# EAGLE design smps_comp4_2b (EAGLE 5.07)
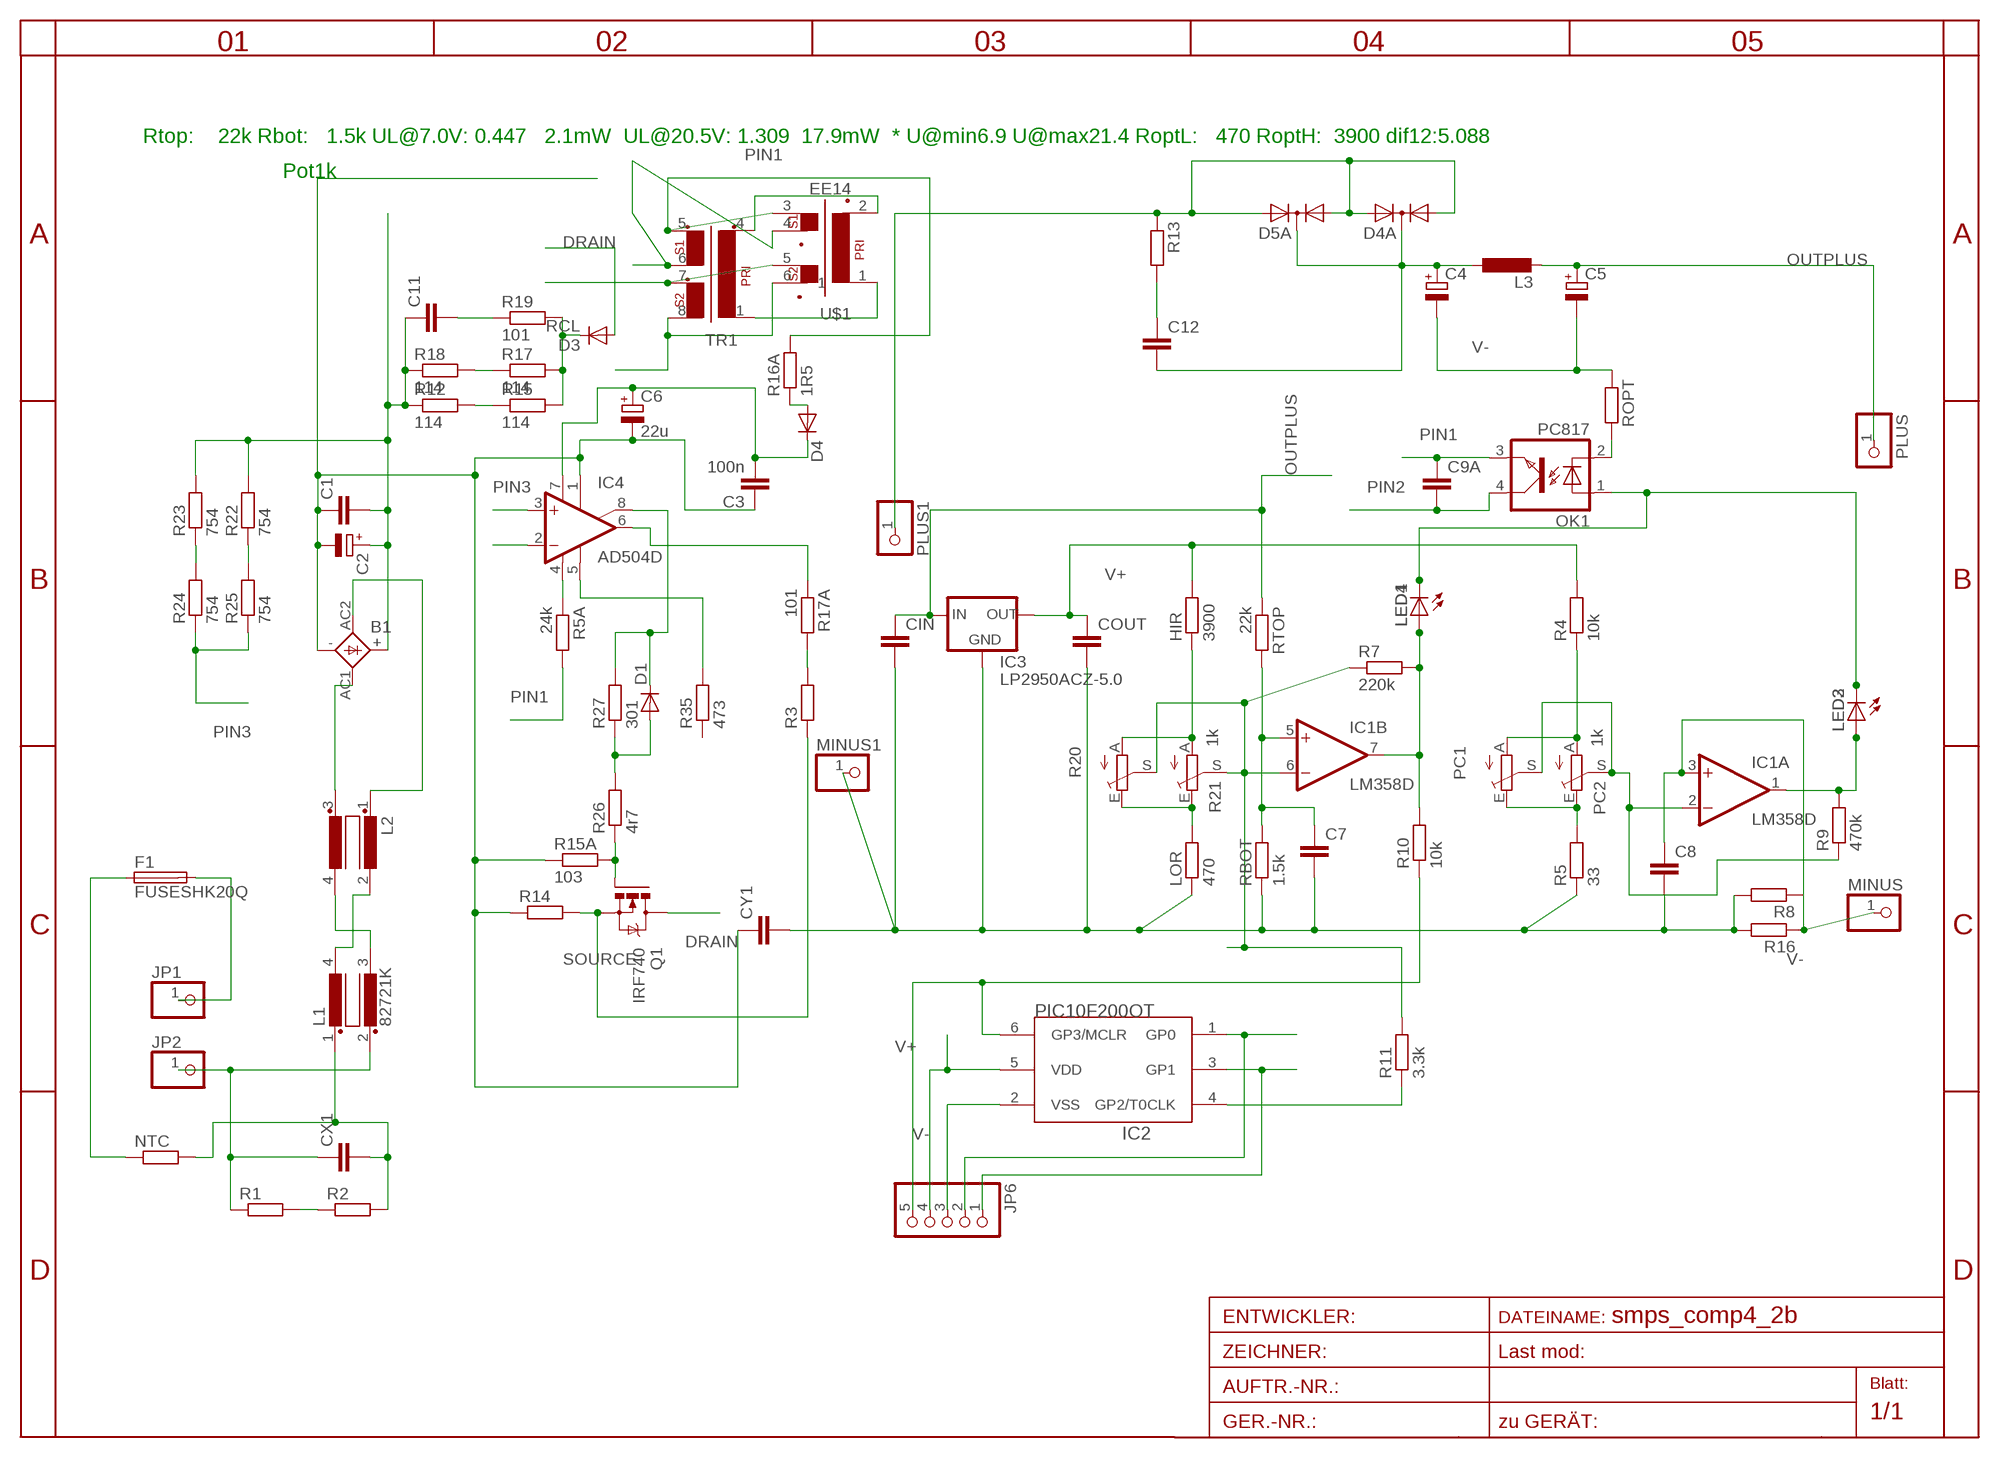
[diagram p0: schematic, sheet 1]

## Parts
B1  KBL  [KBL]
C1  C-EU050-024X044  [C050-024X044]
C2  CPOL-EUE10-25  [EB25D]
C3  100n  C-EUC0805  [C0805]
C4  CPOL-EUE5-8.5  [E5-8,5]
C5  CPOL-EUE5-8.5  [E5-8,5]
C6  22u  CPOL-EUE2.5-6  [E2,5-6]
C7  C-EUC0805  [C0805]
C8  C-EUC0805  [C0805]
C9A  C-EUC0805  [C0805]
C11  C-EUC1206  [C1206]
C12  C-EUC0805  [C0805]
CIN  C-EUC1206  [C1206]
COUT  C-EUC1206  [C1206]
CX1  C-EU150-084X183  [C150-084X183]
CY1  C-EU075-063X106  [C075-063X106]
D1  DIODE-MINIMELF  [MINIMELF]
D3  RCL  1N4004  [DO41-10]
D4  DIODE-MINIMELF  [MINIMELF]
D4A  DIODE-2AC|CAIW220V  [IW220ABS]
D5A  DIODE-2AC|CAIW220V  [IW220ABS]
F1  FUSESHK20Q  [SHK20Q]
HIR  3900  R-EU_R0805  [R0805]
IC1  LM358D  [SO08]
IC2  PIC10F200OT  [SOT23-6]
IC3  LP2950ACZ-5.0  [TO92]
IC4  AD504D  [SO08]
JP1  PINHD-1X12MM2  [1X2MM2]
JP2  PINHD-1X12MM2  [1X2MM2]
JP6  PINHD-1X5/90  [1X05/90]
L1  82721K  [82721K]
L2  R1405VB1/2  [B1/2]
L3  L-EU0207/12  [0207/12]
LED1  LED3MM  [LED3MM]
LED2  LED3MM  [LED3MM]
LED3  LEDCHIPLED_1206  [CHIPLED_1206]
LED4  LEDCHIPLED_1206  [CHIPLED_1206]
LOR  470  R-EU_R0805  [R0805]
MINUS  PINHD-1X12MM2  [1X2MM2]
MINUS1  PINHD-1X11X0.4  [1X01]
NTC  R-EU_0204/7  [0204/7]
OK1  PC817  [DIL04]
PC1  TRIM_EU-S64W  [S64W]
PC2  1k  TRIM_EU-CA6V  [CA6V]
PLUS  PINHD-1X12MM2  [1X2MM2]
PLUS1  PINHD-1X11X0.4  [1X01]
Q1  IRF740  [TO220BV]
R1  R-EU_R1206  [R1206]
R2  R-EU_R1206  [R1206]
R3  R-EU_0207/40  [0207/40]
R4  10k  R-EU_R0805  [R0805]
R5  33  R-EU_R0805  [R0805]
R5A  24k  R-EU_R0805  [R0805]
R7  220k  R-EU_R0805  [R0805]
R8  R-EU_R2010  [R2010]
R9  470k  R-EU_R0805  [R0805]
R10  10k  R-EU_0207/15  [0207/15]
R11  3.3k  R-EU_0207/15  [0207/15]
R12  114  R-EU_R1206  [R1206]
R13  R-EU_R0805  [R0805]
R14  R-EU_0411/3V  [0411V]
R15  114  R-EU_R1206  [R1206]
R15A  103  R-EU_R1206  [R1206]
R16  R-EU_R2010  [R2010]
R16A  1R5  R-EU_R1206  [R1206]
R17  114  R-EU_R1206  [R1206]
R17A  101  R-EU_R0805  [R0805]
R18  114  R-EU_R1206  [R1206]
R19  101  R-EU_R1206  [R1206]
R20  TRIM_EU-S64W  [S64W]
R21  1k  TRIM_EU-CA6V  [CA6V]
R22  754  R-EU_R1206  [R1206]
R23  754  R-EU_R1206  [R1206]
R24  754  R-EU_R1206  [R1206]
R25  754  R-EU_R1206  [R1206]
R26  4r7  R-EU_R1206  [R1206]
R27  301  R-EU_R1206  [R1206]
R35  473  R-EU_R1206  [R1206]
RBOT  1.5k  R-EU_R0805  [R0805]
ROPT  R-EU_R0805  [R0805]
RTOP  22k  R-EU_R0805  [R0805]
TR1  EE20-2  [EE20-2]
U$1  EE14  [EE14]

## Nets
A: PC1.A PC2.A R4.1
A1: HIR.1 R20.A R21.A
CPLUS: C4.+ C12.2 D4A.C D5A.C L3.1
DRAIN: D3.A Q1.D TR1.8 U$1.6
E: PC1.E PC2.E R5.2
E1: LOR.2 R20.E R21.E
N$1: CX1.2 L1.1 NTC.2 R2.2
N$2: CX1.1 JP2.1 L1.2 R1.1
N$3: F1.2A JP1.1
N$5: L1.4 L2.2
N$6: R1.2 R2.1
N$7: B1.AC1(AC2) L2.3
N$9: F1.1A NTC.1
N$10: IC1.6(B:-IN) R7.1 R11.2 R20.S R21.S
N$11: IC1.1(A:OUT) LED2.A LED3.A R9.2
N$12: OK1.2(C) ROPT.2
N$13: LED1.K(C) LED2.K(C) LED3.C LED4.C OK1.1(A)
N$14: L1.3 L2.4
N$15: IC2.6(GP3/MCLR) JP6.5 R10.1
N$16: C7.1 IC1.5(B:+IN) RBOT.2 RTOP.2
N$17: IC2.1(GP0) JP6.2
N$18: IC2.3(GP1) JP6.1
N$19: IC2.4(GP2/T0CLK) R11.1
N$20: B1.AC2(AC1) L2.1
N$21: Q1.G R15A.2 R26.1
N$22: TR1.4 U$1.2
N$23: C11.2 R19.1
N$24: D3.C R15.2 R17.2 R19.2
N$25: D1.A R26.2 R27.1
N$26: R17.1 R18.2
N$27: C12.1 R13.2
N$28: R12.2 R15.1
N$29: R22.1 R25.2
N$30: IC4.4(V-) R5A.1
N$31: R23.1 R24.2
N$32: IC4.6(OUT) R17A.1
N$33: D1.C IC4.8(ON2) R27.2
N$34: R3.2 R17A.2
N$37: D4.A R16A.1
N$38: TR1.1 U$1.1
OUT: C8.1 IC1.3(A:+IN) MINUS.1 R8.1 R16.1
OUTB: IC1.7(B:OUT) LED1.A LED4.A R7.2 R10.2
OUTPLUS: C5.+ CIN.1 IC3.3(IN) L3.2 PLUS.1 RTOP.1
PIN1: B1.- C1.1 C2.- C3.1 C6.- C9A.1 CY1.1 IC4.1(ON1) OK1.3(EMIT) R5A.2 R14.1 R15A.1 TR1.7 U$1.5
PIN2: C9A.2 IC4.2(-IN) OK1.4(COL)
PIN3: IC4.3(+IN) R24.1 R25.1
PIN5: IC4.5(OPT) R35.2
PIN7: C3.2 C6.+ D4.C IC4.7(V+)
PLUS: B1.+ C1.2 C2.+ C11.1 R12.1 R18.1 R22.2 R23.2 TR1.6 U$1.4
S: IC1.2(A:-IN) PC1.S PC2.S R9.1
SOURCE: Q1.S R3.1 R14.2
TPLUS: D4A.A1 D4A.A2 D5A.A1 D5A.A2 PLUS1.1 R13.1
V+: COUT.1 HIR.2 IC2.5(VDD) IC3.1(OUT) JP6.4 R4.2
V-: C4.- C5.- C7.2 C8.2 CIN.2 COUT.2 CY1.2 IC2.2(VSS) IC3.2(GND) JP6.3 LOR.1 MINUS1.1 R5.1 R8.2 R16.2 RBOT.1 ROPT.1
X: R16A.2 TR1.5 U$1.3
Unconnected: R35.1

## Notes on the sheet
- Rtop:    22k Rbot:   1.5k UL@7.0V: 0.447   2.1mW  UL@20.5V: 1.309  17.9mW  * U@min6.9 U@max21.4 RoptL:   470 RoptH:  3900 dif12:5.088
- Pot1k

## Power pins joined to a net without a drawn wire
V+: IC1.8(P:V+)
V-: IC1.4(P:V-)

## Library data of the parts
B1 = rectifier:KBL: DIOTEC RECTIFIER
C1 C3 C7 C8 C9A C11 C12 CIN COUT CX1 CY1 = rcl:C-EU: CAPACITOR, European symbol
C2 C4-C6 = rcl:CPOL-EU: POLARIZED CAPACITOR, European symbol
D1 D4 = diode:DIODE-: DIODE
D3 = diode:1N4004: DIODE
D4A D5A = diode:DIODE-2AC|CA: Dual DIODE Anode-Cathode|Cathode-Anode
F1 = fuse:FUSE: Fuse
HIR LOR NTC R1 R2 R4 R5 R5A R7-R15 R15A R16 R16A R17 R17A R18 R19 R22-R27 R35 RBOT ROPT RTOP = rcl:R-EU_: RESISTOR, European symbol
IC1 = linear:LM358: OP AMP also LM158; LM258; LM2904 Source: http://cache.national.com/ds/LM/LM158.pdf
IC2 = microchip-5:PIC10F20*: uPC nW 0,25/0,5k Program Flash memory
IC3 = v-reg:LP2950?*: Source: http://cache.national.com/ds/LP/LP2950.pdf
IC4 = linear:AD504: OP AMP
JP1 JP2 MINUS MINUS1 PLUS PLUS1 = pinhead:PINHD-1X1: PIN HEADER
JP6 = pinhead:PINHD-1X5: PIN HEADER
L1 = inductors:82721K: FILTER
L2 = inductor-nkl:R1405V: Übertrager (verlustarm) bis typ. 400kHz Power transformer (low loss) up to typ. 400kHz
L3 = rcl:L-EU: INDUCTOR, European symbol
LED1-LED4 = led:LED: LED
OK1 = optocoupler:PC817: SHARP OPTO COUPLER
PC1 PC2 R20 R21 = pot:TRIM_EU-: POTENTIOMETER
Q1 = transistor-power:IRF740: N-CHANNEL MOS FET
R3 = rcl-2:R-EU_: RESISTOR, European symbol
TR1 = trafo:EE20-2: TRANSFORMER 1 primary winding, 2 secondary windings ERA
U$1 = trafo:EE14

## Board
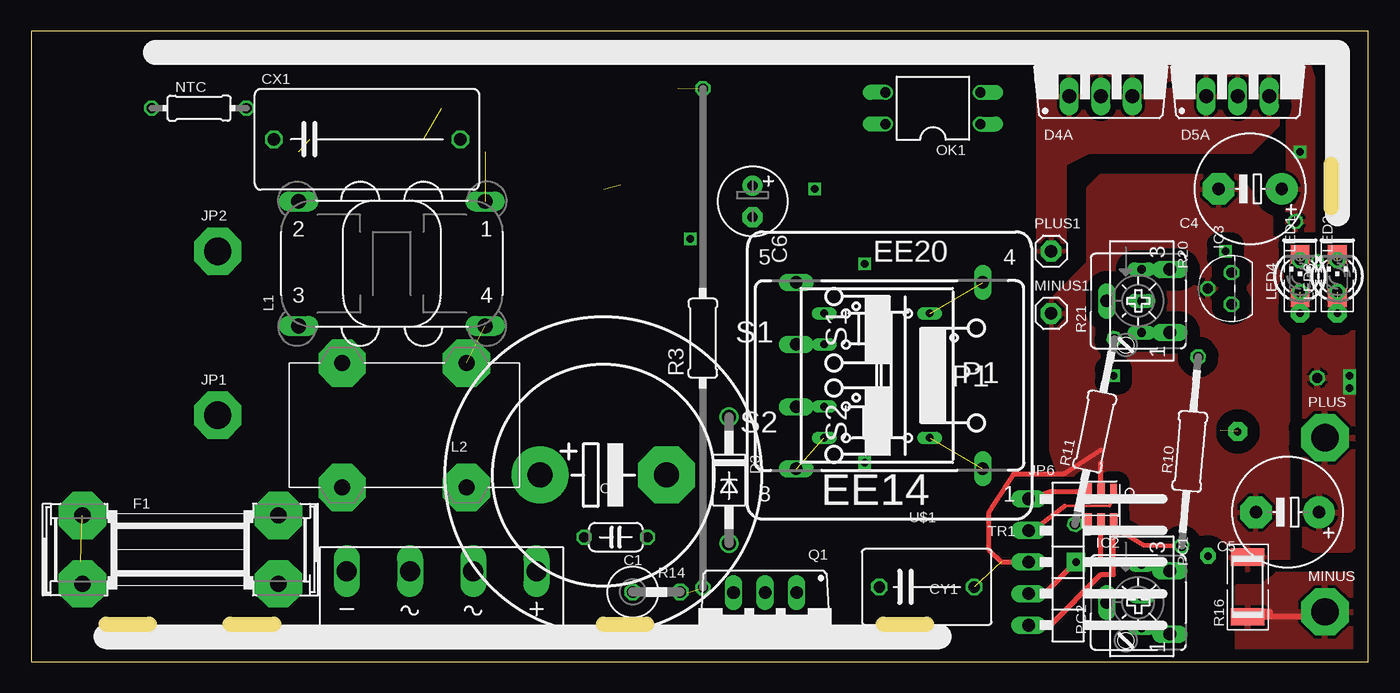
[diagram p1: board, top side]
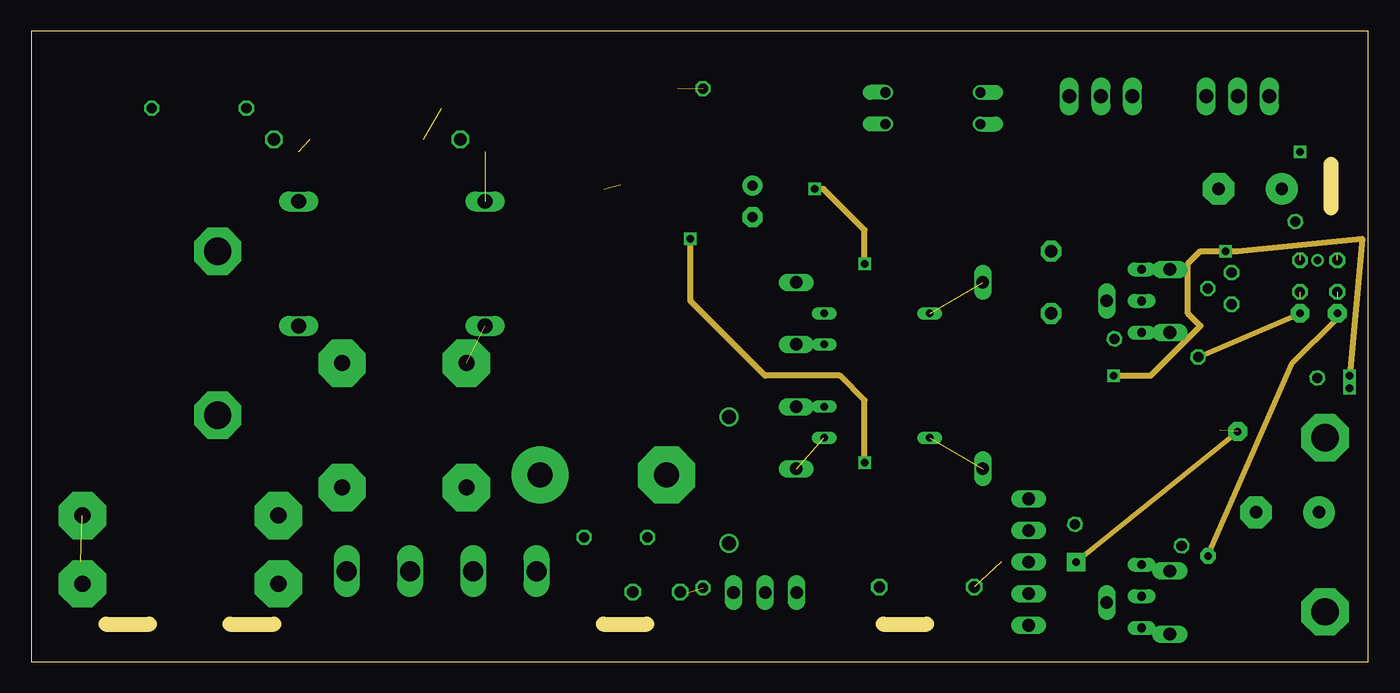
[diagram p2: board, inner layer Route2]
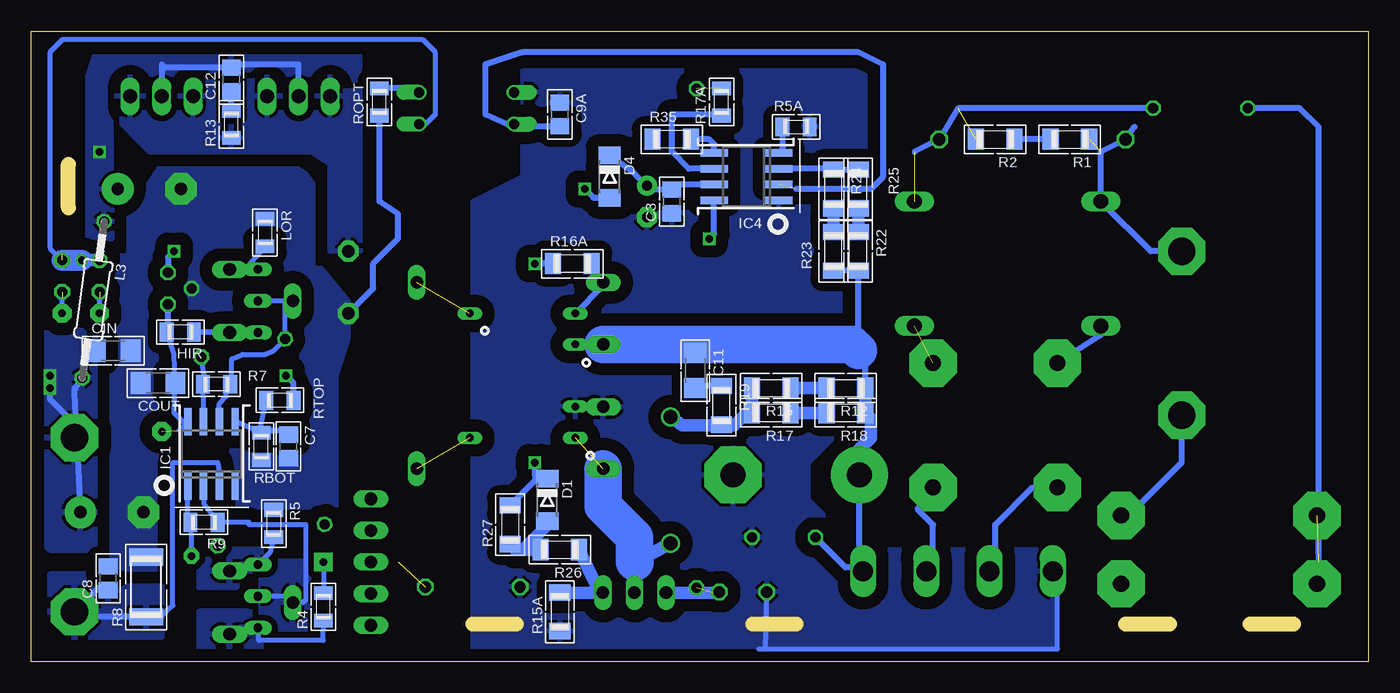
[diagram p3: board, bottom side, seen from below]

Size 107.5 x 50.7 mm. Coordinates in mm from the lower left corner, seen from the top.
Outline: 0,0 107.5,0 107.5,50.7 0,50.7 0,0
Copper layers (1*16): Top 0.035mm / dielectric 1.5mm / Bottom 0.035mm
Design rules "default *": minimum track width 10mil, minimum drill 20mil, track to track 8mil, track to pad 8mil, pad to pad 8mil, via to via 8mil, smd to smd 8mil, copper to edge 40mil, drill to drill 8mil, minimum pad ring 8mil, minimum via ring 8mil, stop-mask expansion 4mil, vias tented up to drill 0mil, thermal gap 10mil
Milling: 5 lines

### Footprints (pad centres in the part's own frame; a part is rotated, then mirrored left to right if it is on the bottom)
KBL = drill 1.6 long: + -7.62,-1.27; - 7.62,-1.27; AC1 2.54,-1.27; AC2 -2.54,-1.27
C050-024X044 = drill 0.813 octagon: 1 -2.54,0; 2 2.54,0
EB25D = drill 2.007 pad 4.597 round: + -5.08,0 | drill 2.007 pad 4.597 octagon: - 5.08,0
C0805 = smd 1.3 x 1.5: 1 -0.95,0; 2 0.95,0
E5-8,5 = drill 1 pad 2.54 round: + -2.54,0 | drill 1 pad 2.54 octagon: - 2.54,0
E2,5-6 = drill 0.8 pad 1.6 round: + -1.27,0 | drill 0.8 pad 1.6 octagon: - 1.27,0
C1206 = smd 1.6 x 1.8: 1 -1.4,0; 2 1.4,0
C150-084X183 = drill 1.016 octagon: 1 -7.493,0; 2 7.493,0
C075-063X106 = drill 0.914 octagon: 1 -3.81,0; 2 3.81,0
MINIMELF = smd 1.4 x 1.8: A 1.7,0; C -1.7,0
DO41-10 = drill 1.118 round: A 5.08,0; C -5.08,0
IW220ABS = drill 1.118 long: A1 -2.54,-2.54; A2 2.54,-2.54; C 0,-2.54
SHK20Q = drill 1.3 pad 3.81 octagon: 1A -7.874,2.75; 1B -7.874,-2.75; 2A 7.874,2.75; 2B 7.874,-2.75
R0805 = smd 1.1 x 1.5: 1 -1.1,0; 2 1.1,0
SO08 = smd 0.6 x 2.2: 1 -1.905,-2.6; 2 -0.635,-2.6; 3 0.635,-2.6; 4 1.905,-2.6; 5 1.905,2.6; 6 0.635,2.6; 7 -0.635,2.6; 8 -1.905,2.6
SOT23-6 = smd 0.55 x 1.2: 1 -1.016,-1.2 | smd 0.6 x 1.27: 2 0,-1.2; 3 1.016,-1.2; 4 1.016,1.2; 5 0,1.2; 6 -1.016,1.2
TO92 = drill 0.813 octagon: 1 -1.27,0; 2 0,1.905; 3 1.27,0
1X2MM2 = drill 2.2 pad 3.81 octagon: 1 0,0
1X05/90 = drill 1.016 long: 1 -5.08,-3.81; 2 -2.54,-3.81; 3 0,-3.81; 4 2.54,-3.81; 5 5.08,-3.81
82721K = drill 1.194 long: 1 7.493,5.004; 2 -7.493,5.004; 3 -7.493,-5.004; 4 7.493,-5.004
B1/2 = drill 1.27 pad 3.81 octagon: 1 -5,5; 2 -5,-5; 3 5,5; 4 5,-5
0207/12 = drill 0.813 octagon: 1 -6.35,0; 2 6.35,0
LED3MM = drill 0.8 pad 1.27 octagon: A -1.27,0; K 1.27,0
CHIPLED_1206 = smd 1.5 x 1.5: A 0,-1.75; C 0,1.75
1X01 = drill 1 pad 1.676 octagon: 1 0,0
0204/7 = drill 0.813 octagon: 1 -3.81,0; 2 3.81,0
DIL04 = drill 0.813 offset: 1 -1.27,-3.81; 2 1.27,-3.81; 3 1.27,3.81; 4 -1.27,3.81
S64W = drill 0.7 long: A 2.54,1.27; E -2.54,1.27; S 0,1.27
CA6V = drill 1.016 long: A -2.54,-2.54; E 2.54,-2.54; S 0,2.54
TO220BV = drill 1.016 long: D 0,-2.54; G -2.54,-2.54; S 2.54,-2.54
R1206 = smd 1.3 x 1.7: 1 -1.55,0; 2 1.55,0
0207/40 = drill 0.813 octagon: 1 -20.08,0; 2 20.08,0
R2010 = smd 1.4 x 2.7: 1 -2.4,0; 2 2.4,0
0207/15 = drill 0.813 octagon: 1 -7.62,0; 2 7.62,0
0411V = drill 0.914 octagon: 1 -2.54,0; 2 1.27,0
EE20-2 = drill 1.016 long: 1 -7.493,7.493; 4 -7.493,-7.493; 5 7.493,-7.493; 6 7.493,-2.515; 7 7.493,2.515; 8 7.493,7.493
EE14 = drill 0.6 pad 1 long: 1 4.25,-5; 2 4.25,5; 3 -4.25,5 | drill 0.6 pad 1.016 long: 4 -4.25,2.5; 5 -4.25,-2.5; 6 -4.25,-5

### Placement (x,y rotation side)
B1  33,6 180 top
C1  47,10 180 top
C2  46,15 0 top
C3  56,37 90 bottom
C4  98,38 180 top
C5  101,12 180 top
C6  58,37 270 top
C7  86.8,17.3 270 bottom
C8  101.3,6.7 90 bottom
C9A  65,44 270 bottom
C11  54.1,23.4 270 bottom
C12  91.4,46.8 90 bottom
CIN  100.9,25 0 bottom
COUT  97.3,22.4 180 bottom
CX1  27,42 0 top
CY1  72,6 0 top
D1  66,13 270 bottom
D3  56.1,14.6 270 top
D4  61,39 270 bottom
D4A  86,48 0 top
D5A  97,48 0 top
F1  12,9 0 top
HIR  95.5,26.5 180 bottom
IC1  93,16.7 0 bottom
IC2  86,12.5 180 top
IC3  96.5,30 90 top
IC4  50,39 90 bottom
JP1  15,19.8 0 top
JP2  15,33 0 top
JP6  84,8 270 top
L1  29,32 0 top
L2  30,19 180 top
L3  102.5,29.1 262 bottom
LED1  102,31 90 top
LED2  105,31 90 top
LED3  105,31 0 top
LED4  102,31 0 top
LOR  88.7,34.5 270 bottom
MINUS  104,4 0 top
MINUS1  82,28 0 top
NTC  13.5,44.5 0 top
OK1  72.5,44.5 90 top
PC1  88,5.25 270 top
PC2  89,4.75 90 top
PLUS  104,18 0 top
PLUS1  82,33 0 top
Q1  59,3 180 top
R1  24,42 180 bottom
R2  30,42 180 bottom
R3  54,26 90 top
R4  84,4.4 90 bottom
R5  88,11.1 270 bottom
R5A  46,43 0 bottom
R7  92.6,22.3 180 bottom
R8  98.25,6 90 bottom
R9  93.6,11.2 180 bottom
R10  93.15,16.9 85 top
R11  85.5,18.5 78 top
R12  42,22 180 bottom
R13  91.4,43.2 90 bottom
R14  50.9,5.6 0 top
R15  48,22 180 bottom
R15A  65,4 90 bottom
R16  97.8,6 90 top
R16A  64,32 0 bottom
R17  48,20 180 bottom
R17A  52,45 90 bottom
R18  42,20 180 bottom
R19  52,20.6 270 bottom
R20  88,29 270 top
R21  89,29 90 top
R22  41,33 270 bottom
R23  43,33 270 bottom
R24  43,38 270 bottom
R25  41,38 270 bottom
R26  65,9 180 bottom
R27  69,11 90 bottom
R35  56,42 0 bottom
RBOT  89,17.3 90 bottom
ROPT  79.5,45 90 bottom
RTOP  87.5,21 180 bottom
TR1  69,23 180 top
U$1  68,23 0 top

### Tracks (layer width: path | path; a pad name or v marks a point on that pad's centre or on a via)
A
  Bottom 0.4: R4.1 84.01,1.7 89.2,1.7 89.2,2.71 PC1.A
  Bottom 0.5: PC1.A PC2.A
  pour Bottom (isolate 0.5, rank 2): 89,4 94,4 94,1 89,1
A1
  Bottom 0.5: R20.A R21.A 92.46,26.46 HIR.1
CPLUS  (via drill 0.6)
  Bottom 0.5: D4A.C 86,48 91.15,48 C12.2 96.75,47.75 97,48 D5A.C
  other vias: 102,41
  pour Bottom (isolate 1): 81,50 102,50 103,47 103,34 101,34 101,37 101.1,46.8 81.1,46.8
  pour Top (isolate 1): 81,50 102,50 103,47 103,34 101,34 101,37 101.1,46.8 81.1,46.8
DRAIN  (1 unrouted)
  Bottom 1: Q1.D 59,7.92 58.96,7.96 D3.A
  Bottom 3: TR1.8 61.51,12.51 59,10 59,8 58.96,7.96
E
  Bottom 0.406: R5.2 88.27,8.8 PC1.E PC2.E
  pour Bottom (isolate 0.5, rank 2): 90,7 89,7 89,9 94,9 94,6 91,6
E1
  Bottom 0.406: LOR.2 90.27,31.6 R20.E
  Bottom 0.5: R20.E R21.E
N$1  (2 unrouted)
  Bottom 0.5: 36.49,41 CX1.2 32.99,44.5 NTC.2
N$2  (1 unrouted)
  Bottom 0.5: 18.81,43 CX1.1 21.51,41 L1.2 17.5,33 JP2.1
N$3
  Bottom 0.5: F1.2A 19.25,11.75 15,16 JP1.1
N$5  (1 unrouted)
N$6
  Bottom 0.5: R1.2 R2.1
N$7
  Bottom 0.5: L2.3 27,14 30,11 30,7.73 B1.AC1
N$9  (1 unrouted)
  Bottom 0.5: NTC.1 5.5,44.5 4,43 4,8 5,7 4,6
N$10
  Bottom 0.4: 91.36,24.34 90.5,24.7 88.7,24.7
  Bottom 0.406: R20.S R21.S 87.08,29 R11.2 87.08,25.92 88,25 88.7,24.7 | IC1.6 92.36,20.73 91.8,21.3 91.8,22 R7.1 91.36,22.43 91.36,24.34
N$11  (via drill 0.6 pad 1.25, 0.6 pad 1.5)  (1 unrouted)
  Route2 0.406: v94.6,8.5 101.4,24 105,27.6 v105,28
  Bottom 0.4: v105,28 LED2.A | 94.6,10.1 R9.2 94.91,11.2 IC1.1
  Bottom 0.406: v94.6,8.5 94.6,10.1
N$12
  Bottom 0.5: ROPT.2 76.64,46.1 OK1.2
N$13  (via drill 0.6)  (2 unrouted)
  Bottom 0.4: OK1.1 75.77,43.23 75,44 75,49 76,50 105,50 106,49 106,33.27 LED2.K
  Bottom 1: v103.4,32.27 LED1.K
  Bottom 1.676: LED2.K v103.4,32.27
N$14
  Bottom 0.5: L1.3 21.51,26.24 L2.4
N$15
  Top 0.406: IC2.6 87.2,10.8 87.5,10.5 | JP6.5 81.92,2.92 86,7 87,7 87,10 87.5,10.5 | R10.1 89.42,9.38 87.5,10.5
N$16
  Bottom 0.4: IC1.5 RBOT.2 87.25,18.6 | C7.1 87.25,18.6 | RTOP.2 89.1,18.65 87.25,18.6
N$17
  Top 0.2: 83.1,12.5 86.7,12.5
  Top 0.254: 86.7,12.5 87,13.18
  Top 0.406: 87.2,13.2 IC2.1 87,13.18 | JP6.2 80.54,10.54 83.1,12.5
N$18
  Top 0.406: JP6.1 81.96,13.68 IC2.3
N$19
  Top 0.406: IC2.4 84.1,11.3 R11.1
N$20
  Bottom 0.5: L2.1 36.25,12.25 35,11 35,7.81 B1.AC2
N$21
  Bottom 1: R26.1 62,6 Q1.G R15A.2
N$22  (1 unrouted)
N$23
  Bottom 0.5: R19.1 53.95,22.15 C11.2
N$24
  Bottom 0.5: R19.2 51.05,19.05 51,19
  Bottom 1: R15.2 R17.2 50,20 51,19 55.12,19 D3.C
N$25
  Bottom 1: 68,9 R26.2 | 68,9 68.55,9 R27.1 | D1.A 66,11 68,9
N$26
  Bottom 1: R18.2 R17.1
N$27
  Bottom 0.5: R13.2 C12.1
N$28
  Bottom 1: R12.2 R15.1
N$29
  Bottom 1: R22.1 R25.2
N$30
  Bottom 0.5: R5A.1 47.1,41.2 IC4.4
N$31
  Bottom 1: R23.1 R24.2
N$32
  Bottom 0.5: IC4.6 54.63,39.63 56,41 56,44 52.1,44 R17A.1
N$33  (via drill 0.6)
  Route2 0.5: v53,34 53,29 59,23 65,23 67,21 v67,16
  Bottom 0.5: IC4.8 52.6,34.4 v53,34 | 67,15 v67,16 | D1.C 66.7,14.7 67,15 | 67,15 67,14.55 R27.2
N$34  (1 unrouted)
N$37  (via drill 0.6)
  Route2 0.5: v67,32 67,34.7 63.7,38 v63,38
  Bottom 0.5: R16A.1 v67,32 | D4.A 62.3,37.3 v63,38
N$38  (1 unrouted)
OUT
  Top 0.5: R16.1 103.6,3.6 MINUS.1 | R16.1 98.8,3.6 | 98,4 99.6,4 R16.1
  Bottom 0.4: IC1.3 92.36,15.27 92.5,16 96.1,16 96.1,4.5 96.6,4.1 97,3.7 98.15,3.7 R8.1
  Bottom 0.5: C8.1 101.25,5.75 101,6 102,6 MINUS.1 103.6,3.6 R8.1
  pour Bottom (isolate 1.016, rank 3): 102,6 103,7 106,7 106,2 97,2 97,6
  pour Top (isolate 1.016, rank 3): 100,7 106,7 106,1 97,1 97,6 99,6
OUTB  (via drill 0.6 pad 1.5)  (1 unrouted)
  Route2 0.406: R10.2 v102,28
  Bottom 0.4: R7.2 93.6,22.6 | v102,28 LED1.A
  Bottom 0.406: IC1.7 93.64,21.07 R7.2 | 93.6,22.6 93.6,23.04 R10.2
OUTPLUS  (via drill 0.6)
  Route2 0.5: v106,23 107,34 97,33 v96,33 94,33 93,32 93,28 94,27 90,23 v87,23
  Bottom 0.5: L3.2 103.95,21.95 104,22 104,21.54 103.88,19.01 | 103.88,19.01 C5.+ | RTOP.1 86.4,22.4 v87,23 | v106,23 106,21.13 103.88,19.01 | IC3.3 96.5,32.5 v96,33
  other vias: 106,22
  pour Bottom (isolate 1, rank 5): 107,28 107,10 106,9 103,9 101,10 101,28
  pour Top (isolate 1, rank 5): 107,28 107,10 106,9 103,9 101,10 101,28
PIN1
  Bottom 0.406: B1.- 25,7.27 25,1 48.46,1 | 48.46,1 49,1 | 48.46,1 R14.1
  pour Bottom (isolate 1): 40,48 68,48 68,39 72,37 72,1 25,1 25,9 42,9 42,10 45,13 45,16 40,21
PIN2  (1 unrouted)
  Bottom 0.5: 46,38 40,38 39,39 39,48 41,49 68,49 71,48 71,44 69.23,43.23 OK1.4 68.51,43.05 C9A.2
PIN3
  Bottom 0.5: IC4.3 43.09,39.63 R24.1 R25.1
PIN5
  Bottom 0.5: IC4.5 52.6,41.6 53,42 R35.2
PIN7
  Bottom 0.5: IC4.7 55.59,38.37 C3.2 57.68,37.95 C6.+ 59.03,39.27 D4.C
PLUS
  Bottom 0.5: 41.52,25.52 41,26.03 R22.2 R23.2 | U$1.4 61.52,25.5 TR1.6 54.12,25.52 C11.1 | R12.1 40.45,24.45 41,25 | 40.92,7.57 C2.+ | B1.+ 40.92,7.57 | 40.92,7.57 42.03,7.57 C1.2
  Bottom 1: C2.+ 40.92,17.08 40,18 40,19.55 R18.1 R12.1
  Bottom 3: TR1.6 41.52,25.52 41,25
S
  Bottom 0.4: IC1.2 93.6,13.4 93.6,12.7 R9.1
  Bottom 0.406: R9.1 90,11.2 90,11 85.4,11 85.4,5 85.65,4.75 PC2.S 86.96,5.25 PC1.S
  pour Bottom (isolate 0.5): 85,8 89,8 89,2 85,2
SOURCE  (1 unrouted)
  Bottom 1: Q1.S 52.73,5.54 R14.2
TPLUS
  pour Bottom (isolate 0.5, rank 2): 81,33 81,46 82,47 100,47 101,46 101,44 98,41 85,41 83.5,40 83.5,33
  pour Top (isolate 0.5, rank 2): 81,33 81,46 82,47 100,47 101,46 101,44 98,41 85,41 83,40 83,33
V+  (via drill 0.6 pad 1.5)  (1 unrouted)
  Top 0.406: IC2.5 86,8 v84,8 81.46,5.46 JP6.4
  Route2 0.406: v84,8 v97,18.5
  Bottom 0.4: HIR.2 96,24.7 COUT.1 96,20 95,19 95,18.7 IC1.8 95.6,18.6 | v84,8 R4.2
  Bottom 0.5: IC3.1 96.5,26.6 HIR.2
V-  (1 unrouted)
  Top 0.406: IC2.2 86,16 | JP6.3 78,8 77,9 77,12 79,15.1 83,15.1 86,17
  Bottom 0.5: ROPT.1 79.5,37 78,36 78,34 80,32 80,30 MINUS1.1
  pour Bottom (isolate 1, rank 4, no thermals): 97,40 86,40 84.5,38 84.5,32 82,29 82,26 83,23 83,8 86,2 101,2 101,34
  pour Top (isolate 1, rank 4): 97,39 86,39 85,38 85,32 82,29 82,17 85,8 86,2 101,2 101,34
X
  Bottom 0.5: R16A.2 62.45,31.44 TR1.5 61.51,30.24 U$1.3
